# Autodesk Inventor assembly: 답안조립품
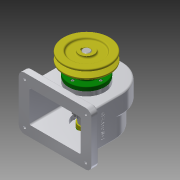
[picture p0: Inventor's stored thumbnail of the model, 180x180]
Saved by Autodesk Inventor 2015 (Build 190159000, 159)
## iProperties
Created: 2017-11
Part Number: 답안조립품
Document SubType Name: Assembly
Designer: 2-PC06
Author: 2-PC06
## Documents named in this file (14)
- C:\Users\2-PC06\Desktop\471108V1013\답안조립품.iam
- C:\Users\2-PC06\Desktop\471108V1013\본체.ipt
- C:\Users\2-PC06\Desktop\471108V1013\축.ipt
- C:\Users\2-PC06\Desktop\471108V1013\베어링 6002.ipt
- C:\Users\2-PC06\Desktop\471108V1013\스퍼기어.ipt
- C:\Users\2-PC06\Desktop\471108V1013\키 - 5 x 5 x 18.ipt
- C:\Users\2-PC06\Desktop\471108V1013\키 - 6 x 6 x 22.ipt
- C:\Users\2-PC06\Desktop\471108V1013\앞커버.ipt
- C:\Users\2-PC06\Desktop\471108V1013\뒤커버.ipt
- C:\Users\2-PC06\Desktop\471108V1013\볼트 M3 x 8.ipt
- C:\Users\2-PC06\Desktop\471108V1013\멈춤나사 - M4 x 10.ipt
- 멈춤나사 - M4 x 10.ipt
- C:\Users\2-PC06\Desktop\471108V1013\V-벨트풀리.ipt
- C:\Users\2-PC06\Desktop\471108V1013\오일 실 15 30 7.ipt
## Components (1 placed, 1 different names)
1. V-벨트풀리:1
